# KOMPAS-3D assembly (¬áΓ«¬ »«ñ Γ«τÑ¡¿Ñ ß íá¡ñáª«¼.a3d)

Referenced files in D:\МОДЕЛЬ ТАНКА Т90\ДЕТАЛИ\ХОДОВАЯ\Каток опорный с балансиром\: каток опорный2.m3d
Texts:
  сборка каток под точение с бандажом
  stalker61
